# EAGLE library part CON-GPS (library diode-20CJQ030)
GPS Connector for the Lassen IQ. A double row surface mounted connector with 1.27mm pitch (0.05")
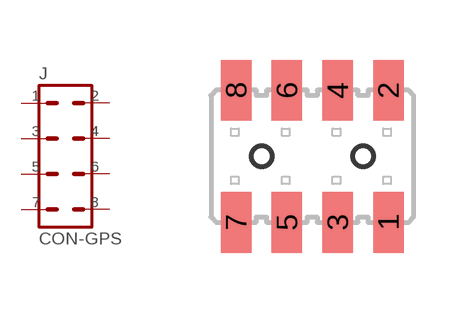
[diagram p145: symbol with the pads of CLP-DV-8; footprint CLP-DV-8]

Designator prefix J

## CON-GPS-A  [CLP-DV-8]
1  1  pas
2  2  pas
3  3  pas
4  4  pas
5  5  pas
6  6  pas
7  7  pas
8  8  pas

## Footprint CLP-DV-8 (pad centres in mm)
Samtech's CLP-104-02 Surface mounted double row connector with 0.05 pitch(1.27mm)
smd 0.762 x 1.524: 1 1.905,-1.651; 2 1.905,1.651; 3 0.635,-1.651; 4 0.635,1.651; 5 -0.635,-1.651; 6 -0.635,1.651; 7 -1.905,-1.651; 8 -1.905,1.651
